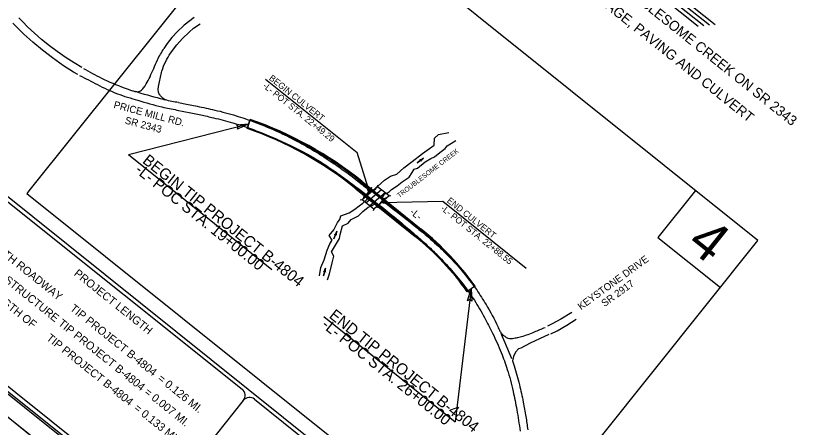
# Model space of a CAD drawing. Extents: x 1732765 to 1738218, y 913652 to 917906.
# Drawn here: x 1733949 to 1735946, y 915055 to 916081 of the extents above; entities that cross this region are included whole.
import ezdxf

# ---------------------------------------------------------------- set-up
doc = ezdxf.new("R2010")
doc.units = 0
for name, color, linetype in [('Default', 7, 'Continuous'), ('Old_Level_23', 7, 'Continuous'), ('Old_Level_3', 7, 'Continuous'), ('Old_Level_38', 7, 'Continuous'), ('Old_Level_5', 7, 'Continuous'), ('Prop DSN Text', 7, 'Continuous'), ('Prop EOT', 7, 'Continuous'), ('Prop Paved Shoulder', 7, 'Continuous'), ('Prop Rip Rap Related Quantities Text', 7, 'Continuous'), ('Prop Roadway Bridge', 7, 'Continuous'), ('Prop Roadway Culvert', 7, 'Continuous'), ('Prop Shade Light', 7, 'Continuous'), ('Sheet Cutting Line CELL', 7, 'Continuous'), ('Sheet Data Field CELL', 7, 'Continuous'), ('Sheet Plot Border Inside CELL', 7, 'Continuous'), ('Sheet Title CELL', 7, 'Continuous')]:
    doc.layers.add(name, color=color, linetype=linetype)

# ---------------------------------------------------------------- blocks, each defined once
blk = doc.blocks.new('EXIST HYDRO RIVER FLOW ARROW')
at = {"layer": 'Default'}
blk.add_line((0, 0), (0, 0), dxfattribs=at)
blk.add_lwpolyline([(0, 0.04575), (0.03775, 0.03), (0.07725, 0.01725), (0.118, 0.00775), (0.159, 0.0015), (0.2, 0), (-0.2, 0), (0.2, 0), (0.159, -0.0015), (0.118, -0.00775), (0.07725, -0.01725), (0.03775, -0.03), (0, -0.04575)], dxfattribs=at)

msp = doc.modelspace()

# ---------------------------------------------------------------- linework, layer by layer
at = {"layer": 'Old_Level_23'}
for p, q in [((1734230.2, 915734.9), (1734588.4, 915448.3)), ((1735086.8, 915399.5), (1735046.7, 915068)), ((1734718.7, 915330.5), (1735046.7, 915068))]:
    msp.add_line(p, q, dxfattribs=at)
at = {"layer": 'Old_Level_3'}
for p, q in [((1734355.4, 915865), (1734375.7, 915860.8)), ((1734375.7, 915860.8), (1734402.4, 915855.5)), ((1734351.5, 915846.2), (1734386.1, 915838.8)), ((1734386.1, 915838.8), (1734411.1, 915834))]:
    msp.add_line(p, q, dxfattribs=at)
for points in [[(1734114.2, 915952), (1734094.4, 915963.9), (1734074.8, 915976.6), (1734052.1, 915992.3), (1734032.8, 916006.6), (1734013.4, 916022.6), (1733995.8, 916037.8), (1733978.4, 916054.2), (1733966.2, 916066.6), (1733956.6, 916076.5)], [(1734394.7, 916077.1), (1734369.9, 916058.3), (1734352, 916041.7), (1734338.9, 916027.2), (1734327.3, 916012.3), (1734319, 915999.9)], [(1734103.9, 915934.7), (1734093.2, 915940.8), (1734068, 915956.5), (1734040.6, 915976.2), (1734015.8, 915995.2), (1733991.1, 916015.8), (1733969, 916035.9), (1733954, 916050.6), (1733941.6, 916063.3)], [(1734335.4, 915988), (1734350.9, 916008.6), (1734365.8, 916025), (1734381.9, 916040.7), (1734393.1, 916050.5), (1734409.2, 916061.5)], [(1735338, 915340.4), (1735310.9, 915323.6), (1735288.9, 915312.4), (1735277.4, 915306.8)], [(1735285.6, 915287.4), (1735301.6, 915294.7), (1735325.5, 915308.7), (1735349.4, 915324)], [(1735280.5, 915285.8), (1735234.1, 915263.7), (1735211.1, 915251.2), (1735205.4, 915250.3), (1735197.8, 915241.5), (1735192.7, 915231), (1735190.2, 915219.7), (1735194.5, 915207.7)]]:
    msp.add_lwpolyline(points, dxfattribs=at)
msp.add_ellipse((1732342.6, 913974.8), major_axis=(-1157.9, 3394.9), ratio=0.865711, start_param=4.786277, end_param=4.805356, dxfattribs=at)
for points in [[(1734117.8, 915950.1), (1734163, 915925.9), (1734219.9, 915901.5), (1734240.2, 915894.4), (1734248.6, 915892.2), (1734256.4, 915892.3), (1734264.8, 915897.6), (1734271.2, 915905.3), (1734274.8, 915911.2), (1734284.3, 915929.4), (1734293.6, 915949.7), (1734302.8, 915971.2), (1734319, 915999.9)], [(1734355.4, 915865), (1734322.6, 915872), (1734317, 915875.3), (1734312.9, 915879.3), (1734308.2, 915884.4), (1734306.9, 915912.1), (1734314.2, 915943.3), (1734323.6, 915967.5), (1734335.4, 915988)], [(1734108.3, 915932.7), (1734152.7, 915909.7), (1734202.8, 915886.9), (1734253.8, 915870.6), (1734314.1, 915853.8), (1734351.5, 915846.2)], [(1734402.4, 915855.5), (1734446, 915846.1), (1734499.3, 915831.9), (1734543.6, 915817), (1734600.1, 915794.3), (1734642.6, 915774.1), (1734700.4, 915743), (1734738.3, 915720.1), (1734776, 915694.3), (1734794, 915680.8), (1734806.8, 915670.4), (1734817.9, 915660.7), (1734834.2, 915645.7)], [(1734411.1, 915834), (1734443, 915826.7), (1734490.9, 915814.1), (1734549.9, 915794.3), (1734596.7, 915774), (1734657.6, 915744.9), (1734684.4, 915729.8), (1734707.5, 915716.8), (1734741.3, 915694.7), (1734765.4, 915678.3), (1734787.6, 915661.5), (1734816.5, 915640), (1734824.7, 915633.5)], [(1734543.6, 915817), (1734596.7, 915795.1), (1734643.1, 915772.7), (1734683.1, 915750.9), (1734729.8, 915721.6), (1734764.7, 915698), (1734803.6, 915668.7), (1734832.5, 915645.7)], [(1734543.6, 915817), (1734596.7, 915795.1), (1734643.1, 915772.7), (1734683.1, 915750.9), (1734729.8, 915721.6), (1734764.7, 915698), (1734803.6, 915668.7), (1734832.5, 915645.7)], [(1734549.9, 915794.3), (1734589.6, 915778.2), (1734633.6, 915758.4), (1734673.1, 915738.4), (1734721.2, 915709.8), (1734758.5, 915684.1), (1734794.6, 915657.6), (1734825.3, 915634.6)], [(1734549.9, 915794.3), (1734589.6, 915778.2), (1734633.6, 915758.4), (1734673.1, 915738.4), (1734721.2, 915709.8), (1734758.5, 915684.1), (1734794.6, 915657.6), (1734825.3, 915634.6)], [(1734865.8, 915621.1), (1734889.6, 915604.8), (1734928.2, 915574.1), (1734968.2, 915540.1), (1735003.2, 915509.4), (1735040.1, 915472.9), (1735067.6, 915441.5), (1735100.7, 915396.8), (1735123.9, 915360.2), (1735153.3, 915305.5), (1735158.8, 915294), (1735163.8, 915287.4), (1735170.7, 915281.1), (1735178.6, 915276.3), (1735186.3, 915275.8), (1735199.8, 915277.7), (1735212.2, 915280.6), (1735245.4, 915292.4), (1735272, 915303.4)], [(1734865.8, 915619.4), (1734899.8, 915592.9), (1734931, 915568.7), (1734948.4, 915554.7), (1734979.8, 915528.3), (1735019.6, 915492), (1735051.5, 915459.1), (1735067.6, 915441.5)], [(1734865.8, 915619.4), (1734899.8, 915592.9), (1734931, 915568.7), (1734948.4, 915554.7), (1734979.8, 915528.3), (1735019.6, 915492), (1735051.5, 915459.1), (1735067.6, 915441.5)], [(1734856.1, 915608.7), (1734893.5, 915576.7), (1734932.1, 915545.3), (1734970.6, 915512.8), (1735003.9, 915482.3), (1735037.8, 915446.3), (1735070.3, 915406.1), (1735094.7, 915371.1), (1735119.9, 915328.1), (1735140.3, 915288.8), (1735161.8, 915240.4), (1735177, 915198.7), (1735191.5, 915143.6), (1735200.8, 915097.7), (1735209.1, 915044.3)], [(1734858, 915608.9), (1734899.1, 915575.6), (1734937, 915543.4), (1734973.3, 915511.8), (1735003.9, 915482.3)], [(1734858, 915608.9), (1734899.1, 915575.6), (1734937, 915543.4), (1734973.3, 915511.8), (1735003.9, 915482.3)], [(1735194.5, 915207.7), (1735207.4, 915160.4), (1735216.9, 915116.7), (1735223.4, 915081), (1735228.1, 915047.9)]]:
    msp.add_spline(points, degree=3, dxfattribs=at)
at = {"layer": 'Old_Level_5'}
for points in [[(1734840.1, 915641.3), (1734847.2, 915648), (1734852.9, 915655.5), (1734870.2, 915671.1), (1734885.5, 915680.9), (1734901, 915686.3), (1734918.3, 915701.7), (1734939.5, 915717.3), (1734965.2, 915737.8), (1734994.5, 915758.7), (1734995.2, 915775.5), (1735005, 915784.7), (1735031.2, 915789.7)], [(1734862.5, 915623.7), (1734870.8, 915637.4), (1734875, 915637.7), (1734882.6, 915642.4), (1734887.6, 915647.4), (1734901.7, 915656.7), (1734914.6, 915666.8), (1734922, 915672.2), (1734931.6, 915678.8), (1734939.7, 915689.9), (1734944.5, 915698.3), (1734952.3, 915700.9), (1734972.1, 915716.7), (1734985.6, 915725.5), (1734995.4, 915729.1), (1735008.3, 915740.3), (1735022.1, 915750), (1735026.9, 915756.7), (1735048.2, 915769.8)], [(1734707.5, 915431.9), (1734711.5, 915453.3), (1734719.2, 915471.7), (1734726.6, 915496), (1734733.3, 915512.2), (1734739.7, 915521.1), (1734732, 915532.8), (1734743.6, 915547.3), (1734752.7, 915565.6), (1734758.3, 915572.5), (1734761, 915582.2), (1734782.1, 915589.7), (1734795.7, 915598.3), (1734806.8, 915606.7), (1734816, 915613.9), (1734826.9, 915623.5), (1734828.1, 915628.2)], [(1734728, 915422.5), (1734732.7, 915436.8), (1734739.8, 915464.3), (1734743.5, 915481.1), (1734737.9, 915491.9), (1734747.8, 915509.1), (1734757.6, 915525.7), (1734759.6, 915535.3), (1734765.1, 915557.2), (1734779.1, 915563.9), (1734786.5, 915572.7), (1734805.3, 915581.7), (1734816.3, 915592.5), (1734829.4, 915603.3), (1734837.8, 915606.7), (1734845.6, 915610.8), (1734852, 915609.7)]]:
    msp.add_lwpolyline(points, dxfattribs=at)
at = {"layer": 'Prop DSN Text'}
for p, q in [((1734572.7, 915923.5), (1734802.3, 915739.7)), ((1734230.2, 915734.9), (1734530.8, 915811.4)), ((1734833.8, 915638.3), (1734802.3, 915739.7)), ((1734837.2, 915652.6), (1734837.4, 915652.5)), ((1734824.5, 915633.6), (1734834, 915645.9)), ((1734834.2, 915645.7), (1734824.7, 915633.5)), ((1734865.8, 915621.1), (1734834.2, 915645.7)), ((1734865.8, 915621.1), (1734834.2, 915645.7)), ((1734817.4, 915628.3), (1734817.3, 915628.5)), ((1734856.1, 915608.7), (1734865.8, 915621.1)), ((1734866, 915621), (1734856.3, 915608.6)), ((1734862.4, 915615.3), (1735016.3, 915618.3)), ((1734873.8, 915626.6), (1734873.9, 915626.4)), ((1735016.3, 915618.3), (1735224.6, 915451.6)), ((1734853.3, 915602.5), (1734853.1, 915602.5))]:
    msp.add_line(p, q, dxfattribs=at)
for points in [[(1734253.6, 915890.6), (1734248.6, 915892.2)], [(1734318, 915872.8), (1734322.6, 915872)], [(1734834, 915645.9), (1734837.1, 915650), (1734836.9, 915650.2), (1734837.2, 915652.6)], [(1734837.4, 915652.5), (1734837.1, 915650.3), (1734837.4, 915650), (1734834.2, 915645.7)], [(1734817.3, 915628.5), (1734820.6, 915629.8), (1734821.7, 915630.2), (1734824.5, 915633.6)], [(1734824.7, 915633.5), (1734821.9, 915629.9), (1734820.7, 915629.6), (1734817.4, 915628.3)], [(1734865.8, 915621.1), (1734856.1, 915608.7), (1734824.7, 915633.5), (1734834.2, 915645.7)], [(1734865.8, 915621.1), (1734856.1, 915608.7), (1734824.7, 915633.5), (1734834.2, 915645.7)], [(1734865.8, 915621.1), (1734868.8, 915625.1), (1734869.2, 915624.8), (1734873.8, 915626.6)], [(1734873.9, 915626.4), (1734869.1, 915624.6), (1734868.8, 915624.8), (1734866, 915621)], [(1734853.1, 915602.5), (1734853.3, 915604.3), (1734852.8, 915604.7), (1734856.1, 915608.7)], [(1734856.3, 915608.6), (1734853.1, 915604.7), (1734853.6, 915604.4), (1734853.3, 915602.5)]]:
    msp.add_lwpolyline(points, dxfattribs=at)
for points in [[(1734500, 915809.1), (1734530.8, 915811.4), (1734502.6, 915798.7), (1734504.9, 915804.8)], [(1734831.4, 915649), (1734832.9, 915637.5), (1734827.6, 915647.8), (1734829.9, 915647)], [(1734832.4, 915649.8), (1734833.8, 915638.3), (1734828.5, 915648.6), (1734830.9, 915647.9)], [(1734872.8, 915612.7), (1734861.4, 915614.5), (1734872.8, 915616.7), (1734871.4, 915614.7)], [(1734873.8, 915613.6), (1734862.4, 915615.3), (1734873.7, 915617.6), (1734872.4, 915615.5)], [(1735077.9, 915370), (1735086.8, 915399.5), (1735088.5, 915368.7), (1735083.6, 915373)]]:
    msp.add_lwpolyline(points, close=True, dxfattribs=at)
msp.add_ellipse((1734702.3, 917450.6), major_axis=(1570.8, -630.8), ratio=0.95853, start_param=4.810004, end_param=4.849482, dxfattribs=at)
at = {"layer": 'Prop EOT'}
for p, q in [((1734527.5, 915801.9), (1734534, 915820.9)), ((1734812.3, 915666.9), (1734960.6, 915547.4)), ((1734799.8, 915651.3), (1734948.1, 915531.8)), ((1735094.9, 915405.3), (1735078.7, 915393.7))]:
    msp.add_line(p, q, dxfattribs=at)
for centre, radius, start, end in [((1734232, 914946.5), 925, 51.1452, 70.9432), ((1734232, 914946.5), 905, 51.1452, 70.9432), ((1734505.8, 914982.8), 725, 35.6458, 51.1452), ((1734505.8, 914982.8), 705, 35.6458, 51.1452)]:
    msp.add_arc(centre, radius, start, end, dxfattribs=at)
at = {"layer": 'Prop Paved Shoulder'}
for p, q in [((1734534, 915820.9), (1734534.7, 915822.7)), ((1734526.9, 915800.1), (1734527.5, 915801.9)), ((1734813.6, 915668.4), (1734961.9, 915549)), ((1734798.5, 915649.7), (1734946.8, 915530.3)), ((1735077.1, 915392.5), (1735078.7, 915393.7)), ((1735096.6, 915406.5), (1735094.9, 915405.3))]:
    msp.add_line(p, q, dxfattribs=at)
for centre, radius, start, end in [((1734232, 914946.5), 927, 51.1452, 70.9432), ((1734232, 914946.5), 903, 51.1452, 70.9432), ((1734505.8, 914982.8), 727, 35.6458, 51.1452), ((1734505.8, 914982.8), 703, 35.6458, 51.1452)]:
    msp.add_arc(centre, radius, start, end, dxfattribs=at)
at = {"layer": 'Prop Rip Rap Related Quantities Text'}
for points in [[(1735803.5, 915520.4), (1734632.4, 916457.7), (1733985, 915648.7)], [(1733985, 915648.7), (1733976.3, 915637.9), (1735147.5, 914700.6), (1735803.5, 915520.4)], [(1735647.4, 915645.4), (1735553.6, 915528.2), (1735709.8, 915403.2)]]:
    msp.add_lwpolyline(points, dxfattribs=at)
at = {"layer": 'Prop Roadway Bridge'}
for p, q in [((1734853, 915654.7), (1734814.6, 915621.9)), ((1734853, 915654.7), (1734854.2, 915659.3)), ((1734862.6, 915647), (1734824.1, 915614.3)), ((1734872.1, 915639.4), (1734833.6, 915606.6)), ((1734881.6, 915631.7), (1734843.2, 915599)), ((1734881.6, 915631.7), (1734886, 915632.5)), ((1734814.6, 915621.9), (1734809, 915621)), ((1734843.2, 915599), (1734841.5, 915594.5))]:
    msp.add_line(p, q, dxfattribs=at)
at = {"layer": 'Prop Roadway Culvert'}
for p, q in [((1734881.6, 915631.7), (1734853, 915654.7)), ((1734843.2, 915599), (1734814.6, 915621.9))]:
    msp.add_line(p, q, dxfattribs=at)
at = {"layer": 'Prop Shade Light'}
for p, q in [((1734534, 915820.9), (1734527.5, 915801.9)), ((1734812.3, 915666.9), (1734960.6, 915547.4)), ((1734948.1, 915531.8), (1734799.8, 915651.3)), ((1735094.9, 915405.3), (1735078.7, 915393.7))]:
    msp.add_line(p, q, dxfattribs=at)
for centre, radius, start, end in [((1734232, 914946.5), 925, 51.1452, 70.9432), ((1734232, 914946.5), 905, 51.1452, 70.9432), ((1734505.8, 914982.8), 725, 35.6458, 51.1452), ((1734505.8, 914982.8), 705, 35.6458, 51.1452)]:
    msp.add_arc(centre, radius, start, end, dxfattribs=at)
at = {"layer": 'Sheet Cutting Line CELL'}
msp.add_line((1732765.3, 916010.8), (1735394.8, 913906.4), dxfattribs=at)
at = {"layer": 'Sheet Data Field CELL'}
msp.add_lwpolyline([(1736769.5, 915624), (1734139.9, 917728.5), (1732765.3, 916010.8), (1735394.8, 913906.4)], close=True, dxfattribs=at)
at = {"layer": 'Sheet Plot Border Inside CELL'}
msp.add_lwpolyline([(1732813.6, 916029.6), (1735415.9, 913947), (1736734.4, 915594.6), (1734132.1, 917677.2)], close=True, dxfattribs=at)
at = {"layer": 'Sheet Title CELL'}
for p, q in [((1735030.9, 916592.4), (1735696.1, 916060)), ((1735032.4, 916578.3), (1735682, 916058.5)), ((1735034, 916564.3), (1735668, 916056.9)), ((1735035.5, 916550.2), (1735653.9, 916055.3)), ((1733396.2, 916056.6), (1735613.6, 914282.1)), ((1733920.9, 915623.9), (1734514.2, 915149)), ((1734517.4, 915121), (1734317.4, 914871.1)), ((1734545.5, 915124.1), (1734990.5, 914767.9))]:
    msp.add_line(p, q, dxfattribs=at)
for points in [[(1733072.9, 915828.7), (1735383.9, 913979.1)], [(1733695.9, 915342.8), (1734289.3, 914868)]]:
    msp.add_lwpolyline(points, dxfattribs=at)
for centre, start, end in [((1734501.8, 915133.5), 321.3297, 51.3297), ((1734533, 915108.5), 51.3297, 141.3297)]:
    msp.add_arc(centre, 20, start, end, dxfattribs=at)

# ---------------------------------------------------------------- block references
at = {"layer": 'Prop DSN Text'}
for p, xscale, yscale, rotation in [((1734959.9, 915720), 49.99999999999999, 49.999999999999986, 36.14802958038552), ((1734747.6, 915534.2), 50, 50, 68.33644777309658), ((1734720.4, 915441.7), 49.99999999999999, 50.00000000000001, 77.07402072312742)]:
    msp.add_blockref('EXIST HYDRO RIVER FLOW ARROW', p, dxfattribs=dict(at, xscale=xscale, yscale=yscale, rotation=rotation))

# ---------------------------------------------------------------- texts
at = {"layer": 'Old_Level_23'}
for s, p in [('BEGIN TIP PROJECT B-4804', (1734263.5, 915716)), ('-L- POC STA. 19+00.00', (1734244.8, 915692.5)), ('END TIP PROJECT B-4804', (1734729.8, 915329.3)), ('-L- POC STA. 26+00.00', (1734711.1, 915305.9))]:
    msp.add_text(s, height=28, rotation=321.3297, dxfattribs=at).set_placement(p)
at = {"layer": 'Old_Level_38'}
for s, p in [('LENGTH ROADWAY', (1733857.4, 915527.8)), ('LENGTH STRUCTURE', (1733827.9, 915490.8)), ('TOTAL LENGTH OF', (1733798.3, 915453.9)), ('TIP PROJECT B-4804', (1734082.7, 915347.5)), ('TIP PROJECT B-4804', (1734053.1, 915310.6)), ('TIP PROJECT B-4804', (1734023.6, 915273.6)), ('= 0.126 MI.', (1734301.4, 915172.5)), ('= 0.007 MI.', (1734268.1, 915138.5)), ('= 0.133 MI.', (1734242.3, 915098.6))]:
    msp.add_text(s, height=20, rotation=321.3297, dxfattribs=at).set_placement(p)
at = {"layer": 'Prop DSN Text'}
for s, height, rotation, p in [('BEGIN CULVERT', 15.75, 321.3297, (1734580.2, 915923.2)), ('-L- POT STA. 22+49.29', 15.75, 321.3297, (1734564.7, 915903.9)), ('PRICE MILL RD.', 18, 345.1573, (1734192, 915851.6)), ('SR 2343', 18, 345.1573, (1734220.2, 915812.6)), ('TROUBLESOME CREEK', 12, 37.5535, (1734907.3, 915626.4)), ('END CULVERT', 15.75, 321.3297, (1735024.8, 915617.3)), ('-L-', 18, 321.3297, (1734932.2, 915588.6)), ('-L- POT STA. 22+88.55', 15.75, 321.3297, (1735009.3, 915598)), ('KEYSTONE DRIVE', 18, 35.9613, (1735361.2, 915346)), ('SR 2917', 18, 35.9613, (1735420.1, 915353.9))]:
    msp.add_text(s, height=height, rotation=rotation, dxfattribs=at).set_placement(p)
at = {"layer": 'Prop Rip Rap Related Quantities Text'}
msp.add_text('4', height=100, rotation=321.3297, dxfattribs=at).set_placement((1735621.8, 915505.7))
at = {"layer": 'Sheet Data Field CELL'}
for s, p in [('BRIDGE NO. 12 OVER TROUBLESOME CREEK ON SR 2343', (1735157.2, 916390.2)), ('GRADING, DRAINAGE, PAVING AND CULVERT', (1735203.4, 916275.7))]:
    msp.add_text(s, height=25, rotation=321.3297, dxfattribs=at).set_placement(p)
at = {"layer": 'Sheet Title CELL'}
msp.add_text('PROJECT LENGTH', height=19.999, rotation=321.3297, dxfattribs=at).set_placement((1734092.6, 915434.9))

doc.saveas('drawing.dxf')
